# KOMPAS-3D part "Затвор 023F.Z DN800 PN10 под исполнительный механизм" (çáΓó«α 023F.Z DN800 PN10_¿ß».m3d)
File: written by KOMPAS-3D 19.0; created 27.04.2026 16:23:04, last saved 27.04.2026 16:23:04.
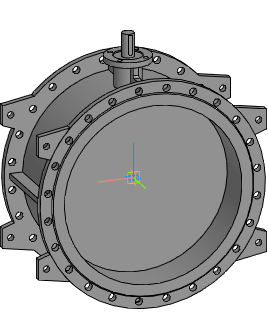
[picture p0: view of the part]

Document properties: Автор: Евгений; Полное имя файла: Z:\3.Личные\kachalov\3d для проектировщиков\1.7 Тип 023F.Z Затвор дисковый поворотный фланцевый с двумя эксцентриками\Затвор 023F.Z DN200-DN1600_исп\_stp_Затвор 023F.Z DN200-DN1600_исп\Затвор 023F.Z DN800 PN10_исп.m3d

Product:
- Part/product: Затвор 023F.Z DN800 PN10 под исполнительный механизм

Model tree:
1. Операция без истории:1  (labels: Затвор 023F.Z DN800 PN10 под исполнительный механизм)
